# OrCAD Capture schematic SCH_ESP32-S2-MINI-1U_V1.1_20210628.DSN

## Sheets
1 01_DesignBlock: title: <ESP32-S2-MINI-1U>; rev: V1.1; note: <01_DesignBlock>
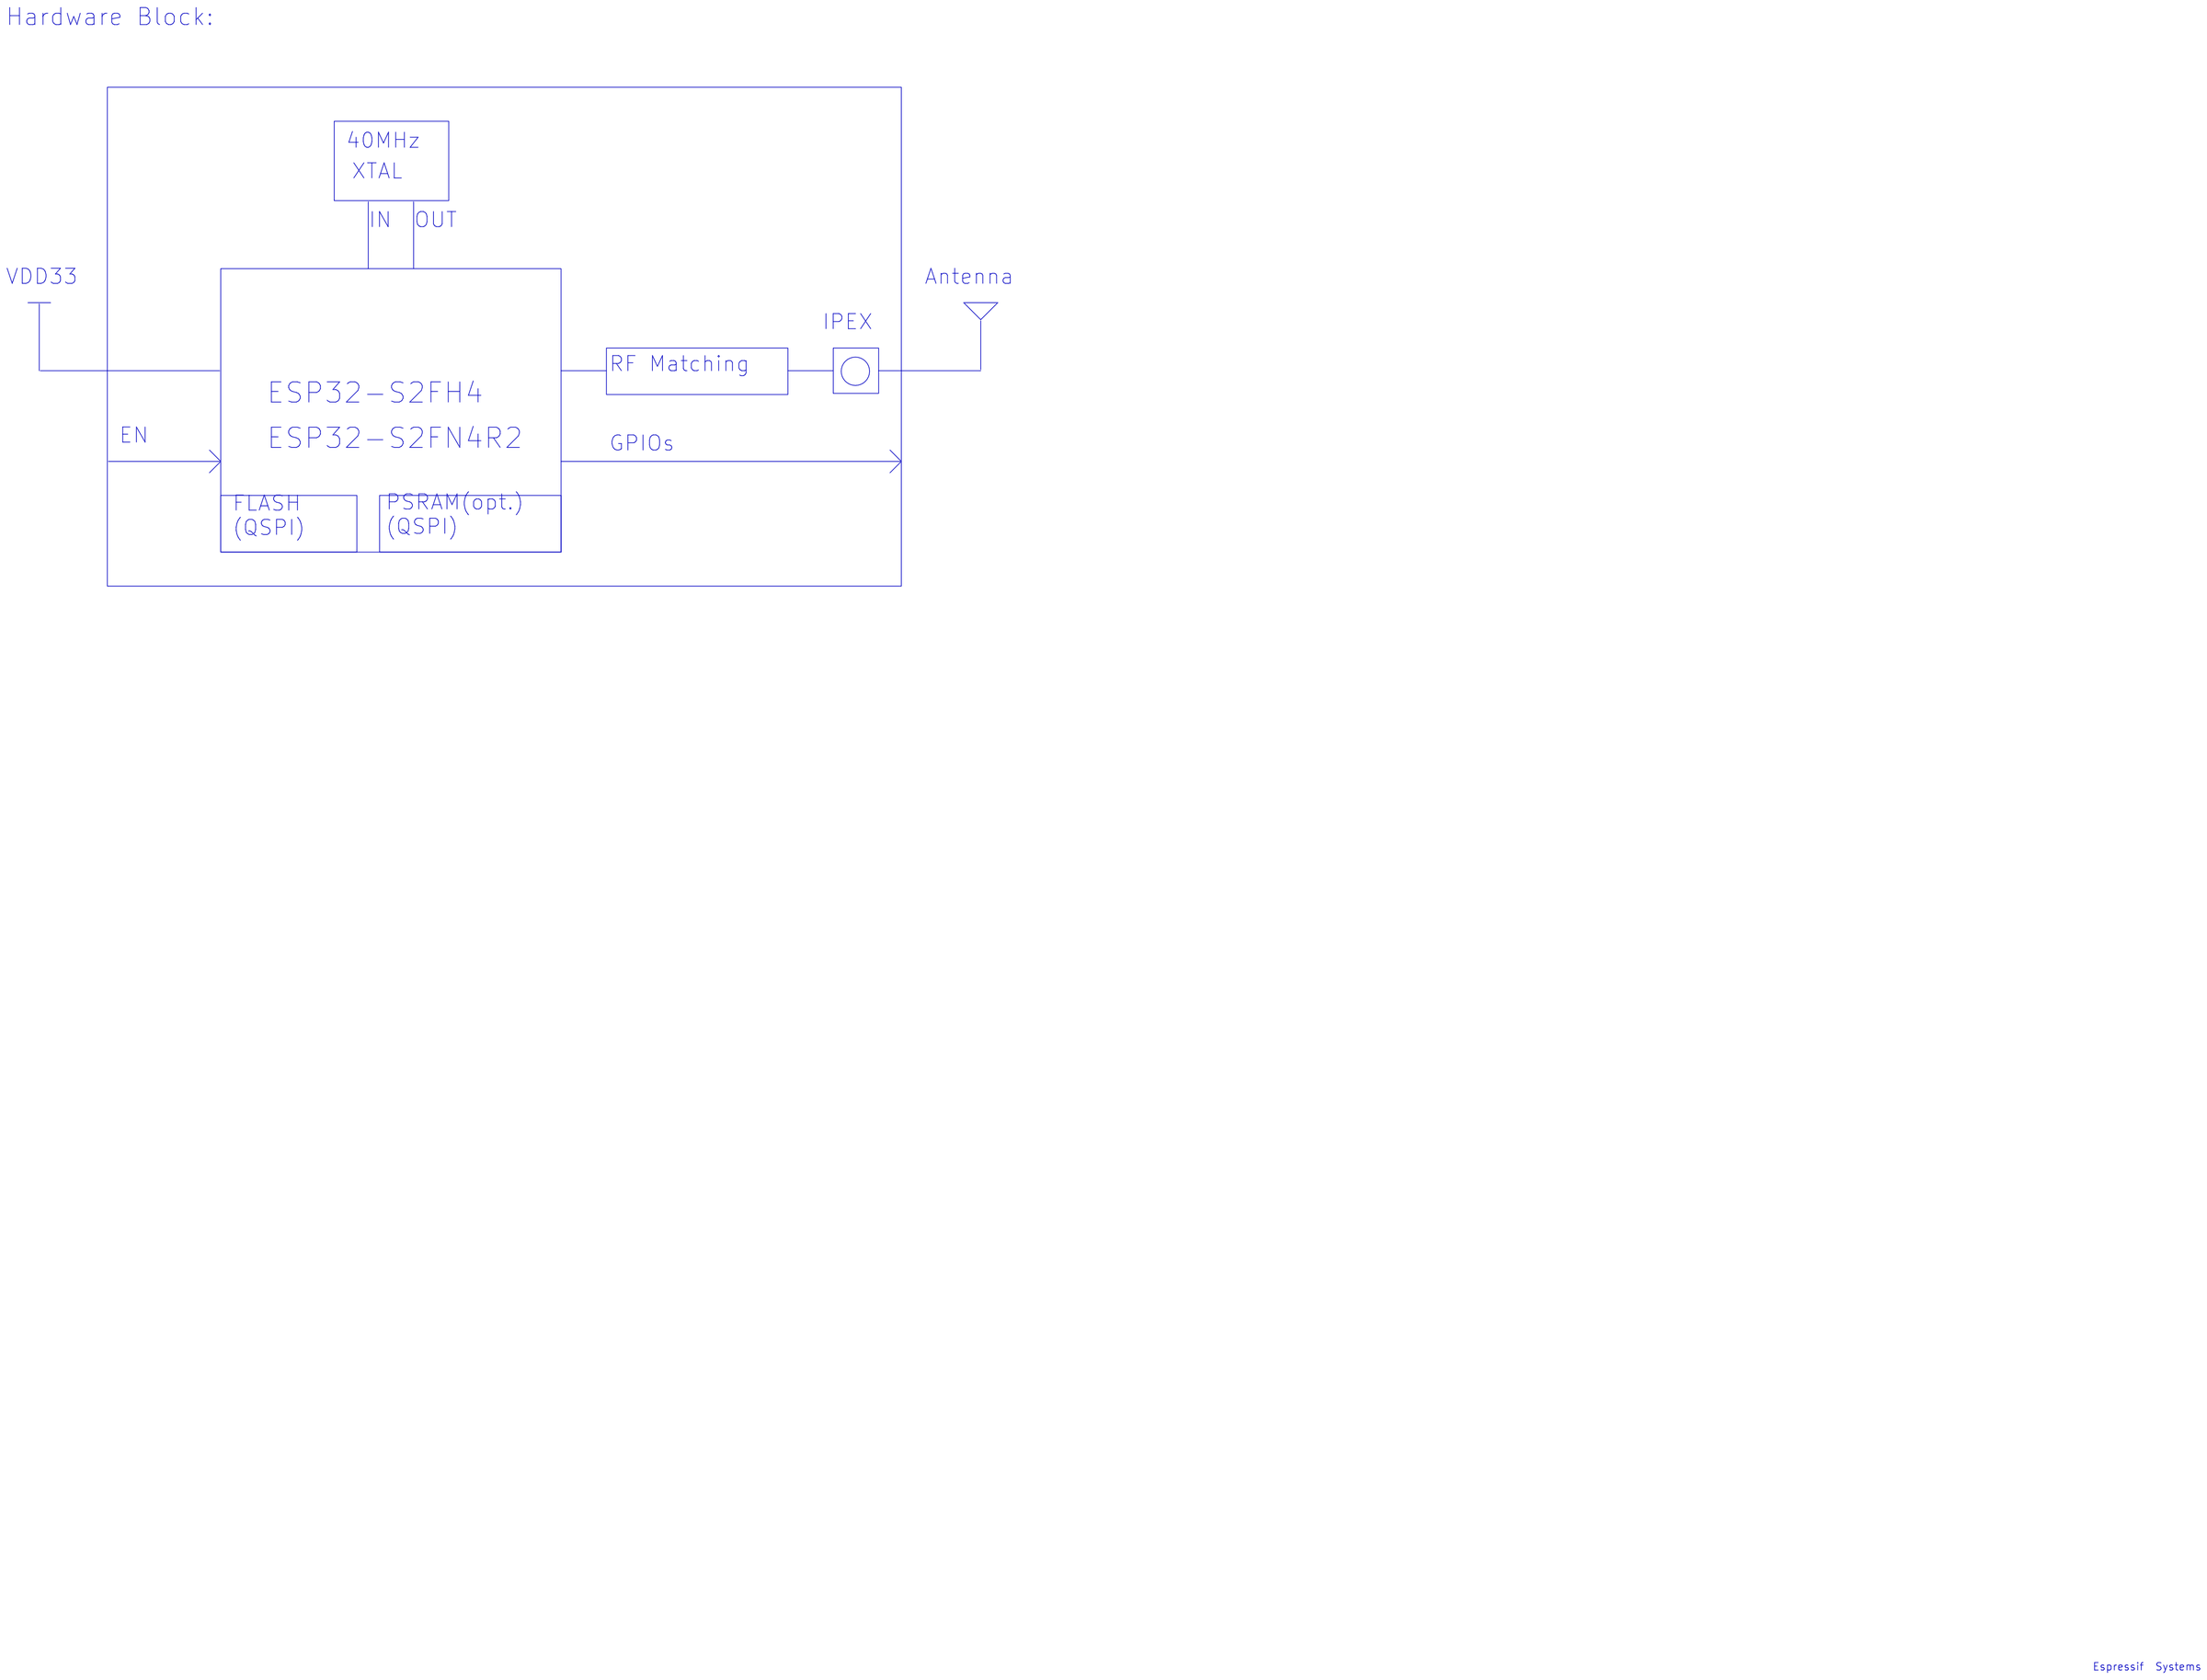
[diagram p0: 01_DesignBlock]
2 02_ESP32-S2-MINI-1U: size A4; note: <02_ESP32-S2-MINI-1U>
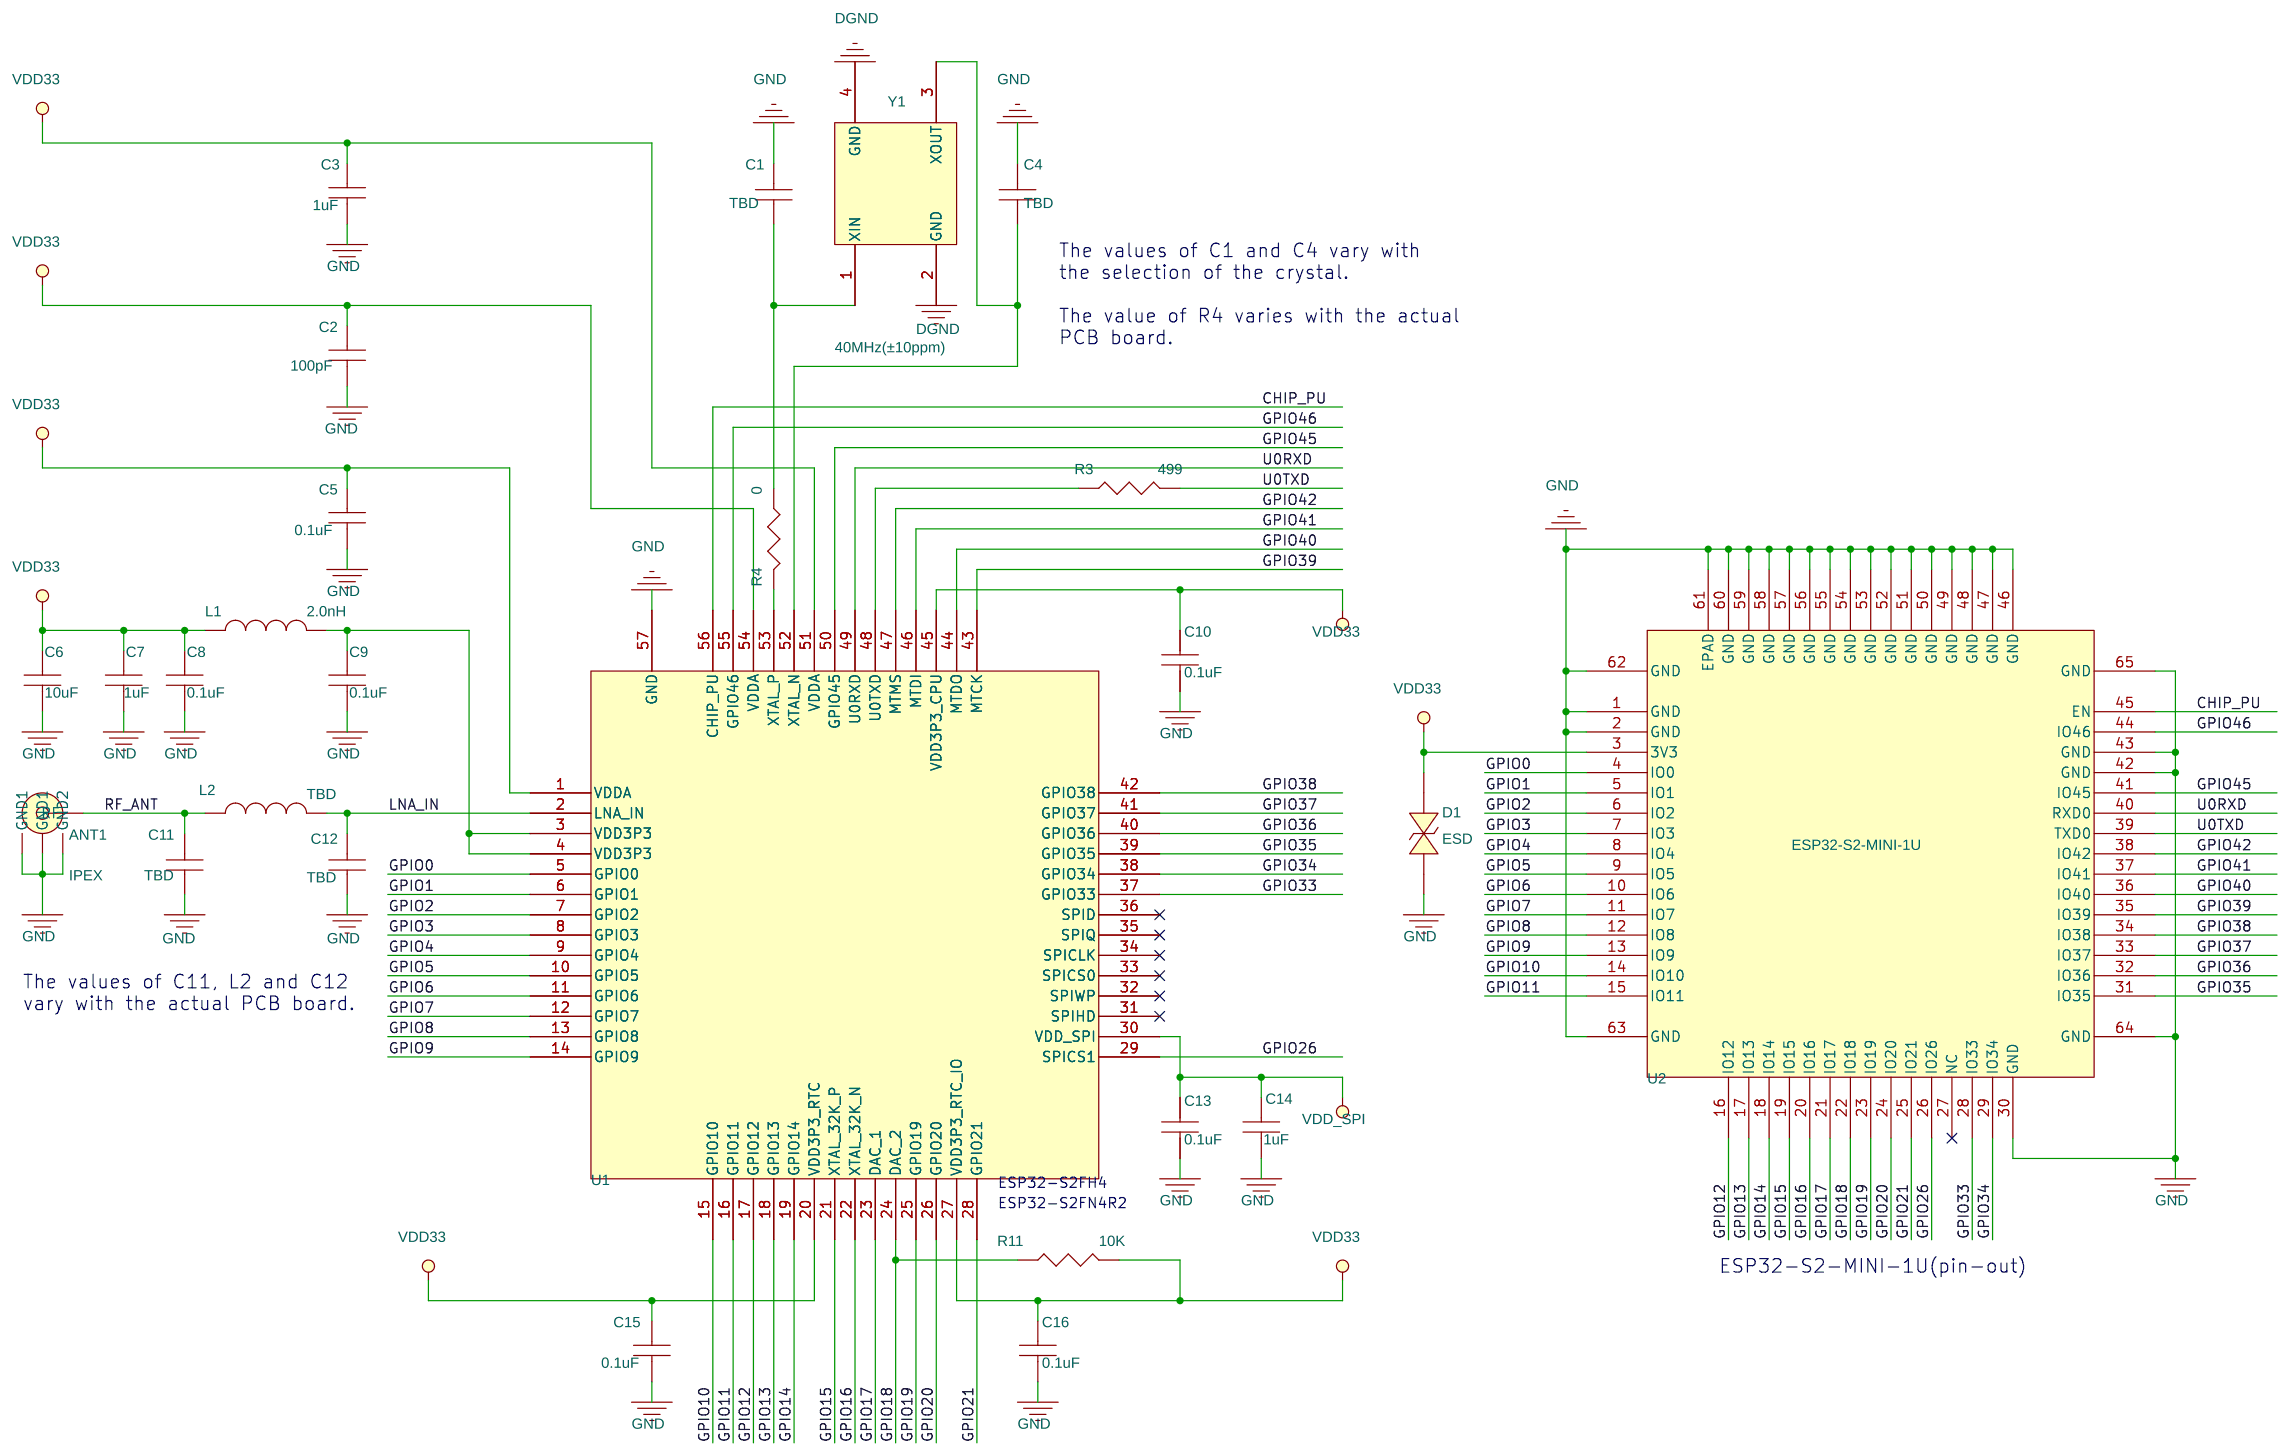
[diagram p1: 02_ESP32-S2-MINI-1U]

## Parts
ANT1  IPEX  [IPEX_4P]
C1  TBD  [C0201]
C2  100pF  [C0201]
C3  1uF  [C0201]
C4  TBD  [C0201]
C5  0.1uF  [C0201]
C6  10uF  [C0402]
C7  1uF  [C0201]
C8  0.1uF  [C0201]
C9  0.1uF  [C0201]
C10  0.1uF  [C0201]
C11  TBD  [C0201]
C12  TBD  [C0201]
C13  0.1uF  [C0201]
C14  1uF  [C0201]
C15  0.1uF  [C0201]
C16  0.1uF  [C0201]
D1  ESD  [SOD882]
L1  2.0nH  [L0201]
L2  TBD  [L0201]
R3  499  [R0201]
R4  0  [R0201]
R11  10K  [R0201]
U1  ESP32-S2FH4/ESP32-S2FN4R2  [QFN56_0P4_7]
U2  ESP32-S2-MINI-1U  [QFN60_0P85_14_MINI]
Y1  40MHz(±10ppm)  [XTAL3225]

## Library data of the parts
ANT1 = IPEX_4P
C1-C16 = CAP
D1 = DIODE_BI-DIR_TRIG
L1 L2 = Inductor
R3 R4 R11 = RESISTOR_0
U1 = ESP32-S2
U2 = ESP32-S2-MINI
Y1 = X1_1

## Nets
GND: ANT1.2(GND2) ANT1.3(GND1) ANT1.4(GND1) C1.2 C2.2 C3.2 C4.2 C5.2 C6.2 C7.2 C8.2 C9.2 C10.2 C11.1 C12.1 C13.2 C14.2 C15.2 C16.2 D1.1 U1.57(GND) U2.1(GND) U2.2(GND) U2.30(GND) U2.42(GND) U2.43(GND) U2.46(GND) U2.47(GND) U2.48(GND) U2.49(GND) U2.50(GND) U2.51(GND) U2.52(GND) U2.53(GND) U2.54(GND) U2.55(GND) U2.56(GND) U2.57(GND) U2.58(GND) U2.59(GND) U2.60(GND) U2.61(EPAD) U2.62(GND) U2.63(GND) U2.64(GND) U2.65(GND) Y1.2(GND) Y1.4(GND)
VDD33: C2.1 C3.1 C5.1 C6.1 C7.1 C8.1 C10.1 C15.1 C16.1 D1.2 L1.1 R11.2 U1.1(VDDA) U1.20(VDD3P3_RTC) U1.27(VDD3P3_RTC_IO) U1.45(VDD3P3_CPU) U1.51(VDDA) U1.54(VDDA) U2.3(3V3)
VDD_SPI: C13.1 C14.1 U1.30(VDD_SPI)
CHIP_PU: U1.56(CHIP_PU) U2.45(EN)
GPIO0: U1.5(GPIO0) U2.4(IO0)
GPIO1: U1.6(GPIO1) U2.5(IO1)
GPIO2: U1.7(GPIO2) U2.6(IO2)
GPIO3: U1.8(GPIO3) U2.7(IO3)
GPIO4: U1.9(GPIO4) U2.8(IO4)
GPIO5: U1.10(GPIO5) U2.9(IO5)
GPIO6: U1.11(GPIO6) U2.10(IO6)
GPIO7: U1.12(GPIO7) U2.11(IO7)
GPIO8: U1.13(GPIO8) U2.12(IO8)
GPIO9: U1.14(GPIO9) U2.13(IO9)
GPIO10: U1.15(GPIO10) U2.14(IO10)
GPIO11: U1.16(GPIO11) U2.15(IO11)
GPIO12: U1.17(GPIO12) U2.16(IO12)
GPIO13: U1.18(GPIO13) U2.17(IO13)
GPIO14: U1.19(GPIO14) U2.18(IO14)
GPIO15: U1.21(XTAL_32K_P) U2.19(IO15)
GPIO16: U1.22(XTAL_32K_N) U2.20(IO16)
GPIO17: U1.23(DAC_1) U2.21(IO17)
GPIO18: R11.1 U1.24(DAC_2) U2.22(IO18)
GPIO19: U1.25(GPIO19) U2.23(IO19)
GPIO20: U1.26(GPIO20) U2.24(IO20)
GPIO21: U1.28(GPIO21) U2.25(IO21)
GPIO26: U1.29(SPICS1) U2.26(IO26)
GPIO33: U1.37(GPIO33) U2.28(IO33)
GPIO34: U1.38(GPIO34) U2.29(IO34)
GPIO35: U1.39(GPIO35) U2.31(IO35)
GPIO36: U1.40(GPIO36) U2.32(IO36)
GPIO37: U1.41(GPIO37) U2.33(IO37)
GPIO38: U1.42(GPIO38) U2.34(IO38)
GPIO39: U1.43(MTCK) U2.35(IO39)
GPIO40: U1.44(MTDO) U2.36(IO40)
GPIO41: U1.46(MTDI) U2.37(IO41)
GPIO42: U1.47(MTMS) U2.38(IO42)
GPIO45: U1.50(GPIO45) U2.41(IO45)
GPIO46: U1.55(GPIO46) U2.44(IO46)
LNA_IN: C12.2 L2.1 U1.2(LNA_IN)
RF_ANT: ANT1.1(RF) C11.2 L2.2
U0RXD: U1.49(U0RXD) U2.40(RXD0)
U0TXD: R3.2 U2.39(TXD0)
N16980501: R3.1 U1.48(U0TXD)
N16981224: C9.1 L1.2 U1.3(VDD3P3) U1.4(VDD3P3)
N16989795: C4.1 U1.52(XTAL_N) Y1.3(XOUT)
N16989829: C1.1 R4.1 Y1.1(XIN)
N17120967: R4.2 U1.53(XTAL_P)

Not connected (* = marked no-connect by the designer): U1 31(SPIHD)* 32(SPIWP)* 33(SPICS0)* 34(SPICLK)* 35(SPIQ)* 36(SPID)*; U2 27(NC)*

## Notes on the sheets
sheet 1
- Hardware Block:
- 40MHz
- XTAL
- IN
- OUT
- VDD33
- Antenna
- IPEX
- RF Matching
- ESP32-S2FH4
- EN
- ESP32-S2FN4R2
- GPIOs
- FLASH
  (QSPI)
- PSRAM(opt.)
  (QSPI)
- Espressif  Systems
sheet 2
- The values of C1 and C4 vary with
  the selection of the crystal.
  The value of R4 varies with the actual
  PCB board.
- The values of C11, L2 and C12
  vary with the actual PCB board.
- ESP32-S2FH4
- ESP32-S2FN4R2
- ESP32-S2-MINI-1U(pin-out)
